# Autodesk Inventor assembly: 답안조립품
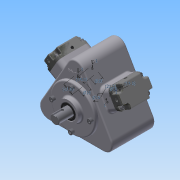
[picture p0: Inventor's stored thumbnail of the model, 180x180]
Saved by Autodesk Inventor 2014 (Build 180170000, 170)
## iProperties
Created: 2015-06
Part Number: 답안조립품
Document SubType Name: Assembly
Designer: Administrator
Mass: 5318.58 g
Surface Area: 2414.93 cm^2
Volume: 1564.62 cm^3
Density: 3.39928 g/cm^3
Author: Administrator
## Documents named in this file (20)
- C:\Documents and Settings\MYHOME\바탕 화면\350605V1043\답안조립품.iam
- C:\Documents and Settings\MYHOME\바탕 화면\350605V1043\본체.ipt
- C:\Documents and Settings\MYHOME\바탕 화면\350605V1043\베어링 NA 4904.ipt
- 베어링 NA 4904.ipt
- C:\Documents and Settings\MYHOME\바탕 화면\350605V1043\편심축.ipt
- C:\Documents and Settings\MYHOME\바탕 화면\350605V1043\앞커버.ipt
- C:\Documents and Settings\MYHOME\바탕 화면\350605V1043\오일실.ipt
- 오일실.ipt
- C:\Documents and Settings\MYHOME\바탕 화면\350605V1043\M6x0.7x20.ipt
- M6x0.7x20.ipt
- C:\Documents and Settings\MYHOME\바탕 화면\350605V1043\부시.ipt
- C:\Documents and Settings\MYHOME\바탕 화면\350605V1043\헤더커버.ipt
- 헤더커버.ipt
- C:\Documents and Settings\MYHOME\바탕 화면\350605V1043\M4x0.5x16.ipt
- M4x0.5x16.ipt
- C:\Documents and Settings\MYHOME\바탕 화면\350605V1043\슬라이드.ipt
- C:\Documents and Settings\MYHOME\바탕 화면\350605V1043\11 - 스프링.ipt
- C:\Documents and Settings\MYHOME\바탕 화면\350605V1043\8 - 스프링.ipt
- C:\Documents and Settings\MYHOME\바탕 화면\350605V1043\9 - 스프링.ipt
- C:\Documents and Settings\MYHOME\바탕 화면\350605V1043\10 - 스프링.ipt
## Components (18 placed, 7 different names)
1. 헤더커버:1
2. 헤더커버:2
3. M4x0.5x16:1
4. M4x0.5x16:2
5. M4x0.5x16:3
6. M4x0.5x16:4
7. M4x0.5x16:5
8. M4x0.5x16:6
9. M4x0.5x16:7
10. M4x0.5x16:8
11. 8 - 스프링:1
12. 9 - 스프링:1
13. 10 - 스프링:1
14. 11 - 스프링:1
15. M6x0.7x20:1
16. M6x0.7x20:2
17. M6x0.7x20:3
18. M6x0.7x20:4
